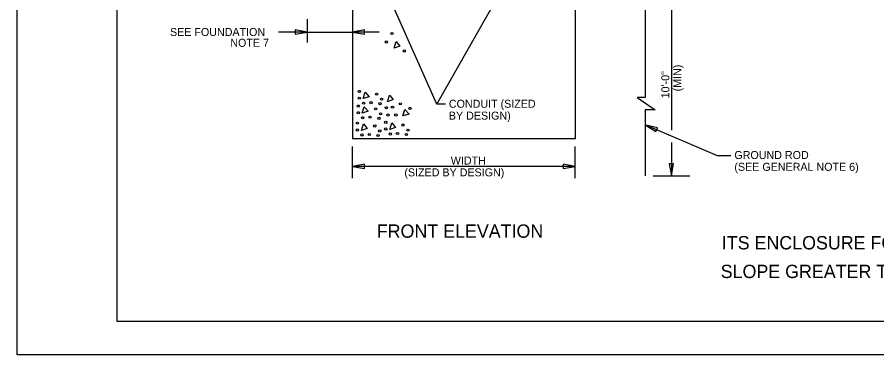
# Model space of a CAD drawing. Extents: x 1299104.8 to 1299141.6, y 239639.8 to 239661.8.
# Drawn here: x 1299104.8 to 1299117.69, y 239639.79 to 239644.86 of the extents above; entities that cross this region are included whole.
import ezdxf

# ---------------------------------------------------------------- set-up
doc = ezdxf.new("R2010")
doc.units = 0
for name, color, linetype in [('GS_plotshape_p', 7, 'Continuous'), ('Level 1', 7, 'Continuous'), ('PTEXT', 7, 'Continuous')]:
    doc.layers.add(name, color=color, linetype=linetype)

msp = doc.modelspace()

# ---------------------------------------------------------------- linework, layer by layer
at = {"layer": 'GS_plotshape_p'}
msp.add_lwpolyline([(1299104.802, 239661.791), (1299138.802, 239661.791), (1299138.802, 239639.791), (1299104.802, 239639.791)], close=True, dxfattribs=at)
at = {"layer": 'Level 1'}
msp.add_lwpolyline([(1299138.302, 239640.291), (1299106.302, 239640.291), (1299106.302, 239661.291), (1299138.302, 239661.291)], close=True, dxfattribs=at)
at = {"layer": 'PTEXT'}
for p, q in [((1299109.829, 239648.067), (1299109.829, 239643.03)), ((1299113.169, 239648.067), (1299113.169, 239643.03)), ((1299114.219, 239645.599), (1299114.219, 239643.649)), ((1299111.092, 239643.553), (1299112.187, 239645.471)), ((1299114.61, 239645.511), (1299114.61, 239643.161)), ((1299109.152, 239644.825), (1299109.152, 239644.478)), ((1299109.152, 239644.633), (1299108.722, 239644.633)), ((1299109.152, 239644.633), (1299108.972, 239644.665)), ((1299108.972, 239644.665), (1299108.972, 239644.601)), ((1299108.972, 239644.601), (1299109.152, 239644.633)), ((1299109.152, 239644.633), (1299109.829, 239644.633)), ((1299110.009, 239644.665), (1299109.829, 239644.633)), ((1299110.23, 239644.633), (1299109.829, 239644.633)), ((1299109.829, 239644.633), (1299110.009, 239644.601)), ((1299110.009, 239644.601), (1299110.009, 239644.665)), ((1299114.219, 239643.465), (1299114.219, 239642.477)), ((1299114.403, 239643.198), (1299114.225, 239643.238)), ((1299114.225, 239643.238), (1299114.379, 239643.139)), ((1299114.379, 239643.139), (1299114.403, 239643.198)), ((1299113.169, 239643.03), (1299109.829, 239643.03)), ((1299109.829, 239642.442), (1299109.829, 239642.917)), ((1299113.169, 239642.442), (1299113.169, 239642.917)), ((1299114.61, 239642.974), (1299114.61, 239642.477)), ((1299110.009, 239642.649), (1299109.829, 239642.617)), ((1299110.009, 239642.585), (1299110.009, 239642.649)), ((1299113.169, 239642.617), (1299112.989, 239642.649)), ((1299112.989, 239642.649), (1299112.989, 239642.585)), ((1299114.578, 239642.657), (1299114.61, 239642.477)), ((1299114.641, 239642.657), (1299114.578, 239642.657)), ((1299114.61, 239642.477), (1299114.641, 239642.657)), ((1299113.169, 239642.617), (1299109.829, 239642.617)), ((1299109.829, 239642.617), (1299110.009, 239642.585)), ((1299112.989, 239642.585), (1299113.169, 239642.617)), ((1299114.335, 239642.477), (1299114.885, 239642.477))]:
    msp.add_line(p, q, dxfattribs=at)
for points in [[(1299111.222, 239643.553), (1299111.092, 239643.553), (1299110.397, 239645.114)], [(1299110.54, 239644.422), (1299110.453, 239644.393), (1299110.482, 239644.491), (1299110.54, 239644.422)], [(1299110.077, 239643.663), (1299109.991, 239643.634), (1299110.02, 239643.732), (1299110.077, 239643.663)], [(1299110.441, 239643.622), (1299110.354, 239643.587), (1299110.383, 239643.686), (1299110.441, 239643.622)], [(1299114.219, 239643.649), (1299114.098, 239643.649), (1299114.366, 239643.465), (1299114.219, 239643.465)], [(1299110.063, 239643.444), (1299109.976, 239643.415), (1299110.005, 239643.513), (1299110.063, 239643.444)], [(1299110.678, 239643.403), (1299110.585, 239643.374), (1299110.614, 239643.472), (1299110.678, 239643.403)], [(1299110.051, 239643.186), (1299109.964, 239643.157), (1299109.993, 239643.255), (1299110.051, 239643.186)], [(1299110.476, 239643.2), (1299110.389, 239643.171), (1299110.418, 239643.27), (1299110.476, 239643.2)], [(1299115.502, 239642.777), (1299115.304, 239642.777), (1299114.225, 239643.238)]]:
    msp.add_lwpolyline(points, dxfattribs=at)
for centre in [(1299110.423, 239644.61), (1299110.337, 239644.483), (1299110.608, 239644.349), (1299109.931, 239643.742), (1299110.19, 239643.7), (1299109.916, 239643.522), (1299109.931, 239643.641), (1299109.997, 239643.566), (1299110.106, 239643.574), (1299110.24, 239643.558), (1299110.265, 239643.625), (1299110.546, 239643.555), (1299109.916, 239643.422), (1299110.176, 239643.48), (1299110.251, 239643.405), (1299110.337, 239643.497), (1299110.362, 239643.388), (1299110.429, 239643.505), (1299110.479, 239643.388), (1299110.691, 239643.487), (1299109.904, 239643.265), (1299109.983, 239643.347), (1299110.092, 239643.355), (1299110.226, 239643.338), (1299110.329, 239643.279), (1299109.904, 239643.164), (1299110.164, 239643.223), (1299110.239, 239643.148), (1299110.329, 239643.179), (1299110.588, 239643.237), (1299110.663, 239643.162), (1299109.971, 239643.089), (1299110.08, 239643.097), (1299110.214, 239643.081), (1299110.396, 239643.103), (1299110.504, 239643.112), (1299110.638, 239643.095)]:
    msp.add_ellipse(centre, major_axis=(0.0177, 0), ratio=0.9, dxfattribs=at)

# ---------------------------------------------------------------- texts
for s, height, p in [('SEE FOUNDATION', 0.12, (1299107.093, 239644.573)), ('NOTE 7', 0.12, (1299107.997, 239644.411)), ('CONDUIT (SIZED', 0.12, (1299111.274, 239643.497)), ('BY DESIGN)', 0.12, (1299111.274, 239643.319)), ('WIDTH', 0.12, (1299111.303, 239642.645)), ('GROUND ROD', 0.12, (1299115.555, 239642.728)), ('(SEE GENERAL NOTE 6)', 0.12, (1299115.555, 239642.551)), ('(SIZED BY DESIGN)', 0.12, (1299110.607, 239642.468)), ('FRONT ELEVATION', 0.2, (1299110.193, 239641.547)), ('ITS ENCLOSURE FOUNDATION, IN EARTH ', 0.2, (1299115.367, 239641.372)), ('SLOPE GREATER THAN OR EQUAL TO 2:1', 0.2, (1299115.35, 239640.942))]:
    msp.add_text(s, height=height, dxfattribs=at).set_placement(p)
for s, p in [('(MIN)', (1299114.758, 239643.742)), ('10\'-0"', (1299114.58, 239643.638))]:
    msp.add_text(s, height=0.12, rotation=90, dxfattribs=at).set_placement(p)

doc.saveas('drawing.dxf')
